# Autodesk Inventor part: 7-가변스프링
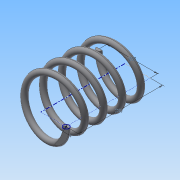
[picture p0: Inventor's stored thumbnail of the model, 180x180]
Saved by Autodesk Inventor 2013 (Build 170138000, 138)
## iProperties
Created: 2015-03
Part Number: 7-가변스프링
Material: 강철, 탄소
Document SubType Name: Modeling
Designer: Administrator
Density: 7.87 g/cm^3
Mass: 48.2733 g
Surface Area: 62.0009 cm^2
Volume: 6.13384 cm^3
Author: Administrator
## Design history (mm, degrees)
sketch "스케치1"
  geometry: L1 (0, 0)-(17.5, 0); L2 (17.5, 0)-(17.5, 43.5); L3 (17.5, 43.5)-(0, 43.5); L4 (0, 43.5)-(0, 0); C1 r 2 at (17.5, 0)
  constraints: 8 end point, 2 parallel, 1 centre point, 1 coincident, 1 horizontal, 1 perpendicular
  dimensions: "d0" = 4 diameter of C1; "d2" = 35 diameter of L2 L4; "d3" = 43.5 distance of L1.end L2.end (derived)
feature "코일1" sketch "스케치1" pitch "d4" = 10; turns "d6" = 4.5; dims "d5" = 43.5 (= d3), "d7" = 0, angle "d8" = 90 deg, angle "d9" = 90 deg, "d10" = 0, "d11" = 0
node "작업 평면1"
sketch "스케치2"
  geometry: L1 (-19.5, 0)-(-15.5, 0) reference; 1 further point
  constraints: 1 horizontal alignment
extrude "돌출1" cut sketch "스케치2" stored distance "d13" = 10; taper "d14" = 0 deg
node "작업 평면2"
sketch "스케치3"
  geometry: L1 (-19.5, 0)-(-15.5, 0) reference; 1 further point
  constraints: 1 horizontal alignment
extrude "돌출2" cut sketch "스케치3" stored distance "d16" = 10; taper "d17" = 0 deg
node "솔리드1"
node "절단 모서리 투영1"
node "절단 모서리 투영2"
other parameters: "d12" = 0, "d15" = -43.5 (= -d3)
